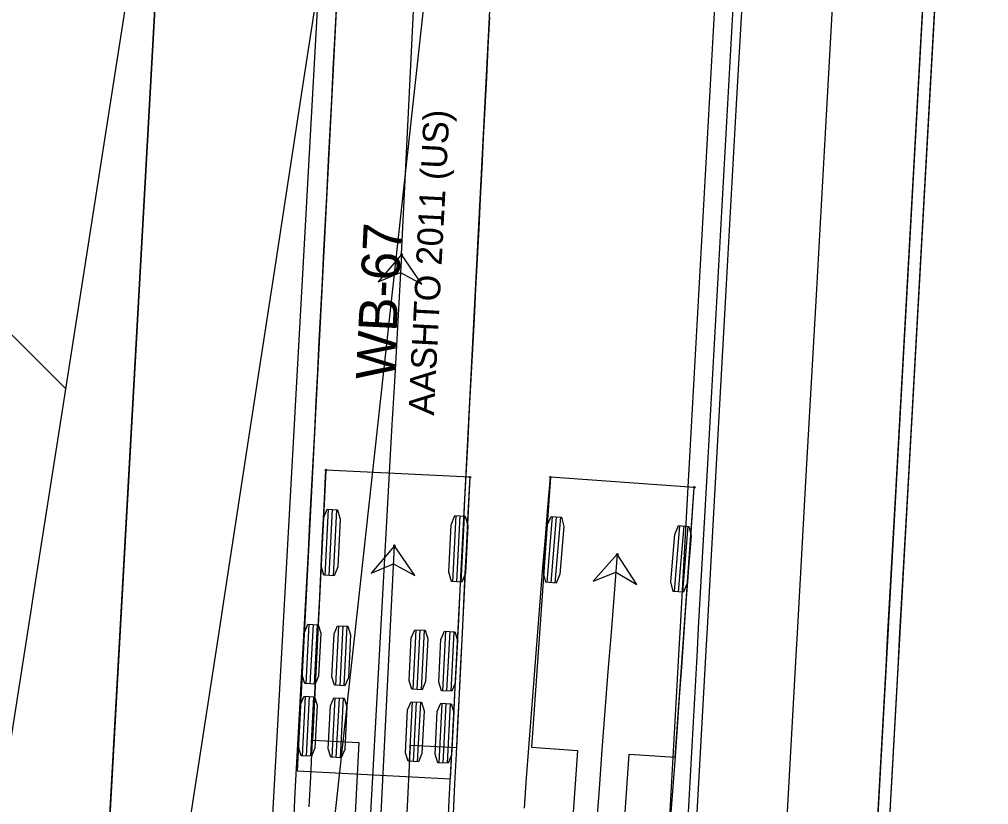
# Model space of a CAD drawing. Extents: x -70 to 701944, y -4 to 666871.
# Drawn here: x 664396.7 to 664450.5, y 657242.7 to 657286.2 of the extents above; entities that cross this region are included whole.
import ezdxf

# ---------------------------------------------------------------- set-up
doc = ezdxf.new("R2010")
doc.units = 0
for name, color, linetype in [('R_Horz Alg', 7, 'Continuous'), ('R_No Plot', 7, 'Continuous'), ('R_Proposed Road', 7, 'Continuous'), ('R_Striping', 7, 'Continuous'), ('T_Indications', 7, 'Continuous'), ('T_Vehicle Path Lt Minor', 7, 'Continuous'), ('T_Vehicle Path Rt', 7, 'Continuous')]:
    doc.layers.add(name, color=color, linetype=linetype)

msp = doc.modelspace()

# ---------------------------------------------------------------- linework, layer by layer
at = {"layer": 'R_Horz Alg'}
msp.add_line((664392.828, 657081.683), (664417.37, 657522.584), dxfattribs=at)
at = {"layer": 'R_No Plot'}
msp.add_line((664414.231, 657304.256), (664408.595, 657203.009), dxfattribs=at)
for points in [[(664346.837, 657236.055), (664352.395, 657335.907), (664406.811, 657332.878), (664401.253, 657233.033)], [(664401.249, 657233.033), (664406.811, 657332.878), (664449.91, 657330.479), (664444.353, 657230.639)]]:
    msp.add_lwpolyline(points, close=True, dxfattribs=at)
at = {"layer": 'R_Proposed Road'}
for points in [[(664429.426, 657181.387), (664429.982, 657191.371), (664430.537, 657201.356), (664431.093, 657211.34), (664431.649, 657221.325), (664432.205, 657231.31), (664432.761, 657241.294), (664433.316, 657251.279), (664433.385, 657252.517), (664433.872, 657261.263), (664434.428, 657271.248), (664434.984, 657281.232), (664435.539, 657291.217), (664436.095, 657301.201), (664436.651, 657311.186), (664437.207, 657321.17), (664437.763, 657331.155), (664438.318, 657341.14)], [(664430.434, 657181.331), (664430.99, 657191.315), (664431.546, 657201.3), (664432.102, 657211.284), (664432.657, 657221.269), (664433.213, 657231.253), (664433.769, 657241.238), (664434.325, 657251.223), (664434.394, 657252.461), (664434.881, 657261.207), (664435.436, 657271.192), (664435.992, 657281.176), (664436.548, 657291.161), (664437.104, 657301.145), (664437.659, 657311.13), (664438.215, 657321.114), (664438.771, 657331.099), (664439.327, 657341.083)], [(664430.924, 657181.303), (664431.479, 657191.288), (664432.035, 657201.273), (664432.591, 657211.257), (664433.147, 657221.242), (664433.702, 657231.226), (664434.258, 657241.211), (664434.814, 657251.195), (664434.883, 657252.434), (664435.37, 657261.18), (664435.926, 657271.164), (664436.481, 657281.149), (664437.037, 657291.133), (664437.593, 657301.118), (664438.149, 657311.103), (664438.704, 657321.087), (664439.26, 657331.072), (664439.816, 657341.056)], [(664435.916, 657181.026), (664436.472, 657191.01), (664437.027, 657200.995), (664437.583, 657210.979), (664438.139, 657220.964), (664438.695, 657230.948), (664439.25, 657240.933), (664439.806, 657250.917), (664439.875, 657252.156), (664440.362, 657260.902), (664440.918, 657270.886), (664441.474, 657280.871), (664442.029, 657290.856), (664442.585, 657300.84), (664443.141, 657310.825), (664443.697, 657320.809), (664444.253, 657330.794), (664444.808, 657340.778)], [(664440.908, 657180.748), (664441.464, 657190.732), (664442.02, 657200.717), (664442.575, 657210.701), (664443.131, 657220.686), (664443.687, 657230.67), (664444.243, 657240.655), (664444.799, 657250.64), (664444.868, 657251.878), (664445.354, 657260.624), (664445.91, 657270.609), (664446.466, 657280.593), (664447.022, 657290.578), (664447.577, 657300.562), (664448.133, 657310.547), (664448.689, 657320.531), (664449.245, 657330.516), (664449.801, 657340.5)], [(664441.574, 657180.711), (664442.129, 657190.695), (664442.685, 657200.68), (664443.241, 657210.664), (664443.797, 657220.649), (664444.353, 657230.633), (664444.908, 657240.618), (664445.464, 657250.602), (664445.533, 657251.841), (664446.02, 657260.587), (664446.576, 657270.572), (664447.132, 657280.556), (664447.687, 657290.541), (664448.243, 657300.525), (664448.799, 657310.51), (664449.355, 657320.494), (664449.91, 657330.479), (664450.466, 657340.463)]]:
    msp.add_lwpolyline(points, dxfattribs=at)
at = {"layer": 'R_Striping'}
for p, q in [((664407.182, 657177.617), (664433.907, 657421.509)), ((664373.463, 657291.555), (664399.316, 657265.701))]:
    msp.add_line(p, q, dxfattribs=at)
for points in [[(664386.492, 657183.777), (664388.047, 657193.706), (664389.601, 657203.635), (664391.155, 657213.564), (664392.709, 657223.493), (664394.263, 657233.422), (664395.818, 657243.351), (664397.372, 657253.279), (664397.565, 657254.511), (664398.926, 657263.208), (664400.48, 657273.137), (664402.035, 657283.066), (664403.589, 657292.995), (664405.143, 657302.924), (664406.697, 657312.853), (664408.252, 657322.782), (664409.806, 657332.711), (664411.36, 657342.64)], [(664397.226, 657183.179), (664398.749, 657193.11), (664400.272, 657203.041), (664401.795, 657212.971), (664403.318, 657222.902), (664404.841, 657232.833), (664406.364, 657242.763), (664407.887, 657252.694), (664408.076, 657253.926), (664409.41, 657262.625), (664410.933, 657272.556), (664412.456, 657282.486), (664413.979, 657292.417), (664415.502, 657302.348), (664417.025, 657312.278), (664418.548, 657322.209), (664420.071, 657332.14), (664421.594, 657342.07)]]:
    msp.add_lwpolyline(points, dxfattribs=at)
at = {"layer": 'T_Indications'}
msp.add_line((664447.679, 657302.394), (664442.044, 657201.147), dxfattribs=at)
at = {"layer": 'T_Vehicle Path Lt Minor'}
for p, q in [((664417.929, 657273.151), (664419.926, 657313.717)), ((664414.863, 657297.455), (664412.143, 657244.525)), ((664420.632, 657244.089), (664423.352, 657297.019)), ((664412.79, 657252.653), (664412.621, 657249.357)), ((664413.019, 657252.641), (664412.85, 657249.345)), ((664413.248, 657252.629), (664413.079, 657249.334)), ((664414.438, 657252.568), (664414.269, 657249.272)), ((664414.667, 657252.556), (664414.498, 657249.261)), ((664414.896, 657252.545), (664414.727, 657249.249)), ((664418.716, 657252.348), (664418.547, 657249.053)), ((664418.945, 657252.337), (664418.775, 657249.041)), ((664419.174, 657252.325), (664419.004, 657249.029)), ((664420.364, 657252.264), (664420.194, 657248.968)), ((664420.593, 657252.252), (664420.423, 657248.956)), ((664420.821, 657252.24), (664420.652, 657248.945)), ((664412.585, 657248.658), (664412.416, 657245.362)), ((664412.814, 657248.646), (664412.645, 657245.351)), ((664413.043, 657248.635), (664412.874, 657245.339)), ((664414.233, 657248.573), (664414.064, 657245.278)), ((664414.462, 657248.562), (664414.292, 657245.266)), ((664414.691, 657248.55), (664414.521, 657245.254)), ((664418.511, 657248.354), (664418.341, 657245.058)), ((664418.74, 657248.342), (664418.57, 657245.046)), ((664418.968, 657248.33), (664418.799, 657245.034)), ((664420.158, 657248.269), (664419.989, 657244.973)), ((664420.387, 657248.257), (664420.218, 657244.962)), ((664420.616, 657248.245), (664420.447, 657244.95)), ((664412.143, 657244.525), (664420.632, 657244.089))]:
    msp.add_line(p, q, dxfattribs=at)
for points in [[(664411.948, 657241.666), (664412.037, 657243.335), (664412.126, 657245.004), (664412.215, 657246.673), (664412.305, 657248.342), (664412.395, 657250.011), (664412.486, 657251.679), (664412.577, 657253.348), (664412.668, 657255.017), (664412.76, 657256.686), (664412.851, 657258.354), (664412.94, 657260.023), (664413.025, 657261.692), (664413.111, 657263.361), (664413.197, 657265.03), (664413.283, 657266.699), (664413.368, 657268.368), (664413.454, 657270.037), (664413.54, 657271.706), (664413.626, 657273.375), (664413.711, 657275.044), (664413.797, 657276.713), (664413.883, 657278.385), (664413.969, 657280.06), (664414.055, 657281.734), (664414.141, 657283.409), (664414.227, 657285.084), (664414.313, 657286.758)], [(664420.488, 657241.239), (664420.574, 657242.906), (664420.661, 657244.573), (664420.747, 657246.24), (664420.834, 657247.907), (664420.921, 657249.574), (664421.007, 657251.242), (664421.094, 657252.909), (664421.181, 657254.576), (664421.267, 657256.243), (664421.354, 657257.91), (664421.44, 657259.577), (664421.527, 657261.244), (664421.614, 657262.911), (664421.7, 657264.578), (664421.787, 657266.246), (664421.874, 657267.913), (664421.96, 657269.58), (664422.047, 657271.247), (664422.133, 657272.914), (664422.219, 657274.581), (664422.304, 657276.249), (664422.39, 657277.922), (664422.475, 657279.6), (664422.561, 657281.278), (664422.646, 657282.956), (664422.73, 657284.633), (664422.815, 657286.311)]]:
    msp.add_lwpolyline(points, dxfattribs=at)
for points in [[(664417.929, 657273.151), (664416.622, 657271.637), (664417.872, 657272.153), (664419.053, 657271.497)], [(664412.734, 657252.656), (664413.305, 657252.626), (664413.453, 657252.156), (664413.331, 657249.783), (664413.136, 657249.331), (664412.564, 657249.36), (664412.416, 657249.83), (664412.538, 657252.203)], [(664414.381, 657252.571), (664414.953, 657252.542), (664415.101, 657252.071), (664414.979, 657249.699), (664414.783, 657249.246), (664414.212, 657249.275), (664414.064, 657249.746), (664414.186, 657252.118)], [(664418.659, 657252.351), (664419.23, 657252.322), (664419.379, 657251.852), (664419.257, 657249.479), (664419.061, 657249.026), (664418.49, 657249.056), (664418.341, 657249.526), (664418.463, 657251.899)], [(664420.307, 657252.267), (664420.878, 657252.237), (664421.027, 657251.767), (664420.905, 657249.394), (664420.709, 657248.942), (664420.138, 657248.971), (664419.989, 657249.441), (664420.111, 657251.814)], [(664412.528, 657248.661), (664413.1, 657248.632), (664413.248, 657248.161), (664413.126, 657245.789), (664412.93, 657245.336), (664412.359, 657245.365), (664412.211, 657245.836), (664412.333, 657248.208)], [(664414.176, 657248.576), (664414.747, 657248.547), (664414.896, 657248.077), (664414.774, 657245.704), (664414.578, 657245.251), (664414.007, 657245.281), (664413.858, 657245.751), (664413.98, 657248.124)], [(664418.454, 657248.357), (664419.025, 657248.327), (664419.174, 657247.857), (664419.052, 657245.484), (664418.856, 657245.032), (664418.285, 657245.061), (664418.136, 657245.531), (664418.258, 657247.904)], [(664420.102, 657248.272), (664420.673, 657248.243), (664420.821, 657247.772), (664420.699, 657245.399), (664420.504, 657244.947), (664419.932, 657244.976), (664419.784, 657245.446), (664419.906, 657247.819)]]:
    msp.add_lwpolyline(points, close=True, dxfattribs=at)
msp.add_circle((664417.929, 657273.151), 0.0417, dxfattribs=at)
msp.add_circle((664417.929, 657273.151), 0.0417, dxfattribs=at)
msp.add_arc((671821.876, 656847.141), 7416.192, 176.7069339, 177.8734926, dxfattribs=at)
at = {"layer": 'T_Vehicle Path Rt'}
for p, q in [((664413.735, 657261.201), (664412.991, 657246.22)), ((664421.725, 657260.804), (664413.735, 657261.201)), ((664413.735, 657261.201), (664413.735, 657261.201)), ((664420.981, 657245.823), (664421.725, 657260.804)), ((664426.174, 657260.802), (664425.121, 657245.839)), ((664434.154, 657260.24), (664426.174, 657260.802)), ((664426.174, 657260.802), (664426.174, 657260.802)), ((664433.101, 657245.277), (664434.154, 657260.24)), ((664413.857, 657259.026), (664413.675, 657255.364)), ((664414.086, 657259.014), (664413.904, 657255.352)), ((664414.315, 657259.003), (664414.133, 657255.341)), ((664420.931, 657258.674), (664420.749, 657255.012)), ((664421.16, 657258.663), (664420.978, 657255.001)), ((664421.389, 657258.652), (664421.207, 657254.99)), ((664426.271, 657258.63), (664425.974, 657254.976)), ((664426.499, 657258.612), (664426.202, 657254.957)), ((664426.728, 657258.593), (664426.431, 657254.939)), ((664433.336, 657258.123), (664433.039, 657254.468)), ((664433.565, 657258.104), (664433.267, 657254.45)), ((664433.793, 657258.086), (664433.496, 657254.431)), ((664410.543, 657116.325), (664417.532, 657257.008)), ((664412.991, 657246.22), (664415.555, 657246.092)), ((664415.555, 657246.092), (664415.029, 657235.505)), ((664417.892, 657235.363), (664418.418, 657245.95)), ((664418.418, 657245.95), (664420.981, 657245.823)), ((664425.121, 657245.839), (664427.681, 657245.659)), ((664427.681, 657245.659), (664426.936, 657235.085)), ((664429.796, 657234.884), (664430.541, 657245.457)), ((664430.541, 657245.457), (664433.101, 657245.277))]:
    msp.add_line(p, q, dxfattribs=at)
for points in [[(664412.808, 657242.532), (664412.891, 657244.199), (664412.974, 657245.866), (664413.056, 657247.533), (664413.139, 657249.2), (664413.222, 657250.867), (664413.305, 657252.534), (664413.388, 657254.2), (664413.47, 657255.867), (664413.553, 657257.534), (664413.636, 657259.201), (664413.719, 657260.868), (664413.735, 657261.201)], [(664420.798, 657242.136), (664420.881, 657243.802), (664420.964, 657245.469), (664421.047, 657247.136), (664421.129, 657248.803), (664421.212, 657250.47), (664421.295, 657252.137), (664421.378, 657253.804), (664421.461, 657255.47), (664421.543, 657257.137), (664421.626, 657258.804), (664421.709, 657260.471), (664421.725, 657260.804)], [(664424.736, 657242.466), (664424.859, 657244.134), (664424.983, 657245.801), (664425.11, 657247.468), (664425.237, 657249.135), (664425.366, 657250.802), (664425.497, 657252.469), (664425.63, 657254.136), (664425.763, 657255.803), (664425.899, 657257.469), (664426.036, 657259.136), (664426.174, 657260.802)], [(664432.855, 657241.977), (664432.978, 657243.637), (664433.102, 657245.297), (664433.219, 657246.957), (664433.336, 657248.617), (664433.453, 657250.278), (664433.57, 657251.938), (664433.687, 657253.599), (664433.804, 657255.259), (664433.921, 657256.919), (664434.037, 657258.58), (664434.154, 657260.24)]]:
    msp.add_lwpolyline(points, dxfattribs=at)
for points in [[(664413.8, 657259.029), (664414.371, 657259), (664414.518, 657258.479), (664414.387, 657255.842), (664414.189, 657255.338), (664413.618, 657255.367), (664413.471, 657255.888), (664413.602, 657258.525)], [(664420.875, 657258.677), (664421.446, 657258.649), (664421.593, 657258.128), (664421.462, 657255.491), (664421.264, 657254.987), (664420.693, 657255.015), (664420.546, 657255.536), (664420.677, 657258.173)], [(664426.214, 657258.635), (664426.784, 657258.589), (664426.915, 657258.063), (664426.701, 657255.432), (664426.487, 657254.934), (664425.917, 657254.98), (664425.787, 657255.506), (664426.001, 657258.137)], [(664433.279, 657258.128), (664433.85, 657258.081), (664433.98, 657257.556), (664433.766, 657254.924), (664433.552, 657254.427), (664432.982, 657254.473), (664432.852, 657254.999), (664433.066, 657257.63)], [(664417.532, 657257.008), (664416.237, 657255.483), (664417.482, 657256.009), (664418.669, 657255.363)], [(664429.883, 657256.531), (664428.541, 657255.048), (664429.802, 657255.534), (664430.968, 657254.851)]]:
    msp.add_lwpolyline(points, close=True, dxfattribs=at)
for centre in [(664413.735, 657261.201), (664421.725, 657260.804), (664426.174, 657260.802), (664434.154, 657260.24), (664417.532, 657257.008), (664429.883, 657256.531)]:
    msp.add_circle(centre, 0.0417, dxfattribs=at)
msp.add_arc((666230.268, 657110.052), 1806.333, 175.348679, 179.761956, dxfattribs=at)

# ---------------------------------------------------------------- texts
at = {"layer": 'T_Vehicle Path Lt Minor'}
for s, height, p in [('AASHTO 2011 (US)', 1.41667, (664419.716, 657264.212)), ('WB-67', 2.125, (664417.511, 657266.16))]:
    msp.add_text(s, height=height, rotation=87.0588, dxfattribs=at).set_placement(p)

doc.saveas('drawing.dxf')
